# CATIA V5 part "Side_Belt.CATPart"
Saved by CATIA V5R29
Part number: Side_Belt
Source: Unknown
Bounding box of the stored display mesh (mm): x -23 to 23, y -30 to 30, z -978 to 978
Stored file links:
  C:\가치같이\SmartFactory_BoxErectorConveyor\Side_Belt.CATPart
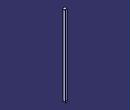
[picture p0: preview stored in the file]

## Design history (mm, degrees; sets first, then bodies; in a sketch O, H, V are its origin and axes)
Body1 (main body)
  Solid1 "PartBody": solid without history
